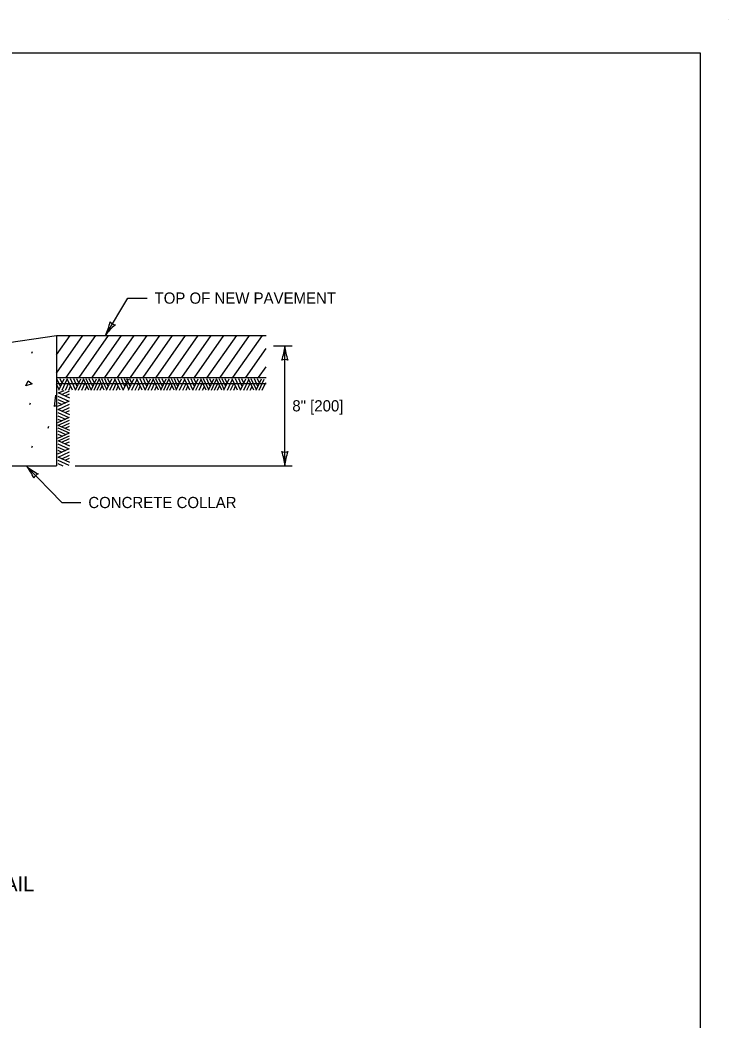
# Model space of a CAD drawing. Extents: x 49991.4 to 50021, y 49987.6 to 50011.4.
# Drawn here: x 50013.11 to 50016.9, y 49993.82 to 49999.18 of the extents above; entities that cross this region are included whole.
import ezdxf

# ---------------------------------------------------------------- set-up
doc = ezdxf.new("R2010")
doc.units = 0
for name, color, linetype in [('Level 1', 7, 'Continuous'), ('Level 2', 7, 'Continuous'), ('Level 3', 7, 'Continuous')]:
    doc.layers.add(name, color=color, linetype=linetype)

msp = doc.modelspace()

# ---------------------------------------------------------------- linework, layer by layer
at = {"layer": 'Level 1'}
for p, q in [((50016.9001, 49999.1756), (50016.9001, 49999.1756)), ((50012.9239, 49997.4313), (50013.3039, 49997.4869)), ((50013.3035, 49997.3834), (50013.3759, 49997.4869)), ((50013.3035, 49997.2853), (50013.4448, 49997.4869)), ((50013.3039, 49997.4869), (50014.4263, 49997.4869)), ((50013.3039, 49997.4869), (50013.3039, 49996.7892)), ((50013.3558, 49997.2621), (50013.5133, 49997.4869)), ((50013.425, 49997.2627), (50013.5817, 49997.4865)), ((50013.4934, 49997.2623), (50013.6507, 49997.4869)), ((50013.5619, 49997.2621), (50013.7193, 49997.4869)), ((50013.6303, 49997.2617), (50013.788, 49997.4869)), ((50013.6767, 49997.4869), (50013.6767, 49997.4869)), ((50013.6992, 49997.2619), (50013.8567, 49997.4869)), ((50013.7678, 49997.2619), (50013.9253, 49997.4869)), ((50013.8365, 49997.2619), (50013.9941, 49997.4869)), ((50013.9052, 49997.2619), (50014.0627, 49997.4869)), ((50013.9738, 49997.2619), (50014.1314, 49997.4869)), ((50014.0425, 49997.2619), (50014.2, 49997.4869)), ((50014.1111, 49997.2619), (50014.2687, 49997.4869)), ((50014.1798, 49997.2619), (50014.3374, 49997.4869)), ((50014.2485, 49997.2619), (50014.406, 49997.4869)), ((50014.3171, 49997.2619), (50014.4263, 49997.4178)), ((50013.1709, 49997.3921), (50013.1752, 49997.4018)), ((50014.3859, 49997.2619), (50014.4263, 49997.3197)), ((50013.3039, 49997.2619), (50013.6773, 49997.2619)), ((50013.325, 49997.2138), (50013.3058, 49997.2549)), ((50013.3157, 49997.1936), (50013.3441, 49997.2549)), ((50013.3332, 49997.2315), (50013.3226, 49997.2549)), ((50013.3885, 49997.1936), (50013.3599, 49997.2549)), ((50013.4052, 49997.1953), (50013.3776, 49997.2549)), ((50013.414, 49997.2143), (50013.3953, 49997.2549)), ((50013.4045, 49997.1936), (50013.4329, 49997.2549)), ((50013.422, 49997.2322), (50013.4117, 49997.2549)), ((50013.4759, 49997.1936), (50013.4472, 49997.2549)), ((50013.4898, 49997.1955), (50013.4622, 49997.2549)), ((50013.498, 49997.2132), (50013.4788, 49997.2549)), ((50013.4889, 49997.1936), (50013.5173, 49997.2551)), ((50013.5066, 49997.2317), (50013.4959, 49997.2549)), ((50013.5594, 49997.1936), (50013.531, 49997.2549)), ((50013.5594, 49997.2263), (50013.5462, 49997.2549)), ((50013.5805, 49997.2138), (50013.5613, 49997.2549)), ((50013.5712, 49997.1936), (50013.5996, 49997.2549)), ((50013.5887, 49997.2315), (50013.578, 49997.2549)), ((50013.6439, 49997.1936), (50013.6154, 49997.2549)), ((50013.6607, 49997.1953), (50013.6331, 49997.2549)), ((50013.6695, 49997.2143), (50013.6508, 49997.2549)), ((50013.6599, 49997.1936), (50013.6883, 49997.2549)), ((50013.6775, 49997.2322), (50013.6672, 49997.2549)), ((50013.6773, 49997.2619), (50014.4263, 49997.2619)), ((50013.6984, 49997.2138), (50013.6792, 49997.2549)), ((50013.6891, 49997.1936), (50013.7175, 49997.2549)), ((50013.7066, 49997.2315), (50013.696, 49997.2549)), ((50013.7619, 49997.1936), (50013.7333, 49997.2549)), ((50013.7786, 49997.1953), (50013.751, 49997.2549)), ((50013.7874, 49997.2143), (50013.7687, 49997.2549)), ((50013.7779, 49997.1936), (50013.8063, 49997.2549)), ((50013.7954, 49997.2322), (50013.7851, 49997.2549)), ((50013.8493, 49997.1936), (50013.8206, 49997.2549)), ((50013.8632, 49997.1955), (50013.8356, 49997.2549)), ((50013.8714, 49997.2132), (50013.8522, 49997.2549)), ((50013.8623, 49997.1936), (50013.8907, 49997.2551)), ((50013.88, 49997.2317), (50013.8693, 49997.2549)), ((50013.9328, 49997.1936), (50013.9044, 49997.2549)), ((50013.9328, 49997.2263), (50013.9196, 49997.2549)), ((50013.9539, 49997.2138), (50013.9347, 49997.2549)), ((50013.9446, 49997.1936), (50013.973, 49997.2549)), ((50013.9621, 49997.2315), (50013.9514, 49997.2549)), ((50014.0173, 49997.1936), (50013.9888, 49997.2549)), ((50014.0341, 49997.1953), (50014.0065, 49997.2549)), ((50014.0429, 49997.2143), (50014.0242, 49997.2549)), ((50014.0333, 49997.1936), (50014.0617, 49997.2549)), ((50014.0509, 49997.2322), (50014.0406, 49997.2549)), ((50014.1048, 49997.1936), (50014.076, 49997.2549)), ((50014.1187, 49997.1955), (50014.0911, 49997.2549)), ((50014.1269, 49997.2132), (50014.1076, 49997.2549)), ((50014.1177, 49997.1936), (50014.1461, 49997.2551)), ((50014.1355, 49997.2317), (50014.1248, 49997.2549)), ((50014.1882, 49997.1936), (50014.1598, 49997.2549)), ((50014.1882, 49997.2263), (50014.1751, 49997.2549)), ((50014.2094, 49997.2138), (50014.1901, 49997.2549)), ((50014.2, 49997.1936), (50014.2284, 49997.2549)), ((50014.2176, 49997.2315), (50014.2069, 49997.2549)), ((50014.2728, 49997.1936), (50014.2442, 49997.2549)), ((50014.2896, 49997.1953), (50014.2619, 49997.2549)), ((50014.2983, 49997.2143), (50014.2797, 49997.2549)), ((50014.2888, 49997.1936), (50014.3172, 49997.2549)), ((50014.3063, 49997.2322), (50014.296, 49997.2549)), ((50014.3602, 49997.1936), (50014.3315, 49997.2549)), ((50014.3741, 49997.1955), (50014.3465, 49997.2549)), ((50014.3823, 49997.2132), (50014.3631, 49997.2549)), ((50014.3732, 49997.1936), (50014.4016, 49997.2551)), ((50014.3909, 49997.2317), (50014.3802, 49997.2549)), ((50013.3039, 49997.2304), (50013.6773, 49997.2304)), ((50013.3174, 49997.1974), (50013.3039, 49997.2263)), ((50013.334, 49997.1936), (50013.3612, 49997.2521)), ((50013.3515, 49997.1936), (50013.37, 49997.2334)), ((50013.3689, 49997.1936), (50013.3786, 49997.2147)), ((50013.4214, 49997.1936), (50013.4485, 49997.2519)), ((50013.439, 49997.1936), (50013.4573, 49997.2334)), ((50013.4569, 49997.1936), (50013.4662, 49997.2141)), ((50013.5041, 49997.1936), (50013.5315, 49997.253)), ((50013.5209, 49997.1936), (50013.5399, 49997.2353)), ((50013.5371, 49997.1936), (50013.5481, 49997.2178)), ((50013.5729, 49997.1974), (50013.5594, 49997.2263)), ((50013.5895, 49997.1936), (50013.6167, 49997.2521)), ((50013.607, 49997.1936), (50013.6255, 49997.2334)), ((50013.6243, 49997.1936), (50013.634, 49997.2147)), ((50013.6773, 49997.2304), (50014.4263, 49997.2304)), ((50013.6908, 49997.1974), (50013.6773, 49997.2263)), ((50013.7074, 49997.1936), (50013.7346, 49997.2521)), ((50013.7249, 49997.1936), (50013.7434, 49997.2334)), ((50013.7423, 49997.1936), (50013.752, 49997.2147)), ((50013.7948, 49997.1936), (50013.8219, 49997.2519)), ((50013.8124, 49997.1936), (50013.8307, 49997.2334)), ((50013.8303, 49997.1936), (50013.8396, 49997.2141)), ((50013.8775, 49997.1936), (50013.9049, 49997.253)), ((50013.8943, 49997.1936), (50013.9133, 49997.2353)), ((50013.9105, 49997.1936), (50013.9215, 49997.2178)), ((50013.9463, 49997.1974), (50013.9328, 49997.2263)), ((50013.9629, 49997.1936), (50013.9901, 49997.2521)), ((50013.9804, 49997.1936), (50013.9989, 49997.2334)), ((50013.9977, 49997.1936), (50014.0074, 49997.2147)), ((50014.0503, 49997.1936), (50014.0774, 49997.2519)), ((50014.0678, 49997.1936), (50014.0861, 49997.2334)), ((50014.0857, 49997.1936), (50014.0951, 49997.2141)), ((50014.133, 49997.1936), (50014.1604, 49997.253)), ((50014.1497, 49997.1936), (50014.1688, 49997.2353)), ((50014.1659, 49997.1936), (50014.177, 49997.2178)), ((50014.2017, 49997.1974), (50014.1882, 49997.2263)), ((50014.2183, 49997.1936), (50014.2456, 49997.2521)), ((50014.2358, 49997.1936), (50014.2543, 49997.2334)), ((50014.2532, 49997.1936), (50014.2629, 49997.2147)), ((50014.3058, 49997.1936), (50014.3328, 49997.2519)), ((50014.3233, 49997.1936), (50014.3416, 49997.2334)), ((50014.3412, 49997.1936), (50014.3505, 49997.2141)), ((50014.3884, 49997.1936), (50014.4159, 49997.253)), ((50014.4052, 49997.1936), (50014.4242, 49997.2353)), ((50013.311, 49997.1807), (50013.3723, 49997.1523)), ((50013.311, 49997.1624), (50013.3695, 49997.1351)), ((50013.3148, 49997.179), (50013.3437, 49997.1925)), ((50013.3312, 49997.1713), (50013.3723, 49997.1906)), ((50013.3489, 49997.1631), (50013.3723, 49997.1738)), ((50013.1601, 49997.1171), (50013.1644, 49997.1268)), ((50013.311, 49997.1449), (50013.3508, 49997.1264)), ((50013.311, 49997.1079), (50013.3723, 49997.1365)), ((50013.311, 49997.1275), (50013.3321, 49997.1178)), ((50013.3127, 49997.0911), (50013.3723, 49997.1188)), ((50013.3317, 49997.0824), (50013.3723, 49997.101)), ((50013.311, 49997.0919), (50013.3723, 49997.0635)), ((50013.311, 49997.0749), (50013.3693, 49997.0479)), ((50013.311, 49997.0574), (50013.3508, 49997.0391)), ((50013.311, 49997.0205), (50013.3723, 49997.0492)), ((50013.3496, 49997.0744), (50013.3723, 49997.0847)), ((50013.2586, 49996.9915), (50013.2629, 49997.0013)), ((50013.311, 49997.0395), (50013.3315, 49997.0302)), ((50013.311, 49997.0075), (50013.3725, 49996.9791)), ((50013.311, 49996.9923), (50013.3704, 49996.9648)), ((50013.3129, 49997.0065), (50013.3723, 49997.0342)), ((50013.3306, 49996.9984), (50013.3723, 49997.0176)), ((50013.3491, 49996.9898), (50013.3723, 49997.0005)), ((50013.311, 49996.9755), (50013.3527, 49996.9564)), ((50013.311, 49996.937), (50013.3723, 49996.9654)), ((50013.311, 49996.9593), (50013.3352, 49996.9483)), ((50013.3148, 49996.9235), (50013.3437, 49996.937)), ((50013.3312, 49996.9159), (50013.3723, 49996.9351)), ((50013.3437, 49996.937), (50013.3723, 49996.9502)), ((50013.1709, 49996.8864), (50013.1752, 49996.8961)), ((50013.311, 49996.9252), (50013.3723, 49996.8968)), ((50013.311, 49996.9069), (50013.3695, 49996.8797)), ((50013.311, 49996.8894), (50013.3508, 49996.8709)), ((50013.311, 49996.8524), (50013.3723, 49996.881)), ((50013.3489, 49996.9077), (50013.3723, 49996.9183)), ((50013.311, 49996.8721), (50013.3321, 49996.8623)), ((50013.311, 49996.8364), (50013.3723, 49996.808)), ((50013.3127, 49996.8357), (50013.3723, 49996.8633)), ((50013.3317, 49996.8269), (50013.3723, 49996.8456)), ((50013.3496, 49996.8189), (50013.3723, 49996.8292)), ((50012.8258, 49996.7892), (50013.3039, 49996.7892)), ((50013.311, 49996.8195), (50013.3693, 49996.7924)), ((50013.311, 49996.802), (50013.3374, 49996.7899))]:
    msp.add_line(p, q, dxfattribs=at)
msp.add_lwpolyline([(49999.3835, 49998.9992), (50016.7501, 49998.9992), (50016.7501, 49987.7988), (49999.3835, 49987.7988)], close=True, dxfattribs=at)
for points in [[(50013.1386, 49997.2173), (50013.1516, 49997.2443), (50013.1733, 49997.2281), (50013.1386, 49997.2173)], [(50013.2918, 49997.1059), (50013.3004, 49997.1678), (50013.3039, 49997.1641)], [(50013.3039, 49997.1114), (50013.2928, 49997.1063)]]:
    msp.add_lwpolyline(points, dxfattribs=at)
at = {"layer": 'Level 3'}
for p, q in [((50013.565, 49997.4869), (50013.6858, 49997.6869)), ((50013.6858, 49997.6869), (50013.7885, 49997.6869)), ((50014.4663, 49997.4313), (50014.5663, 49997.4313)), ((50014.5263, 49996.7892), (50014.5263, 49997.4313)), ((50013.1407, 49996.7892), (50013.3311, 49996.5927)), ((50013.4039, 49996.7892), (50014.5663, 49996.7892)), ((50013.3311, 49996.5927), (50013.4338, 49996.5927))]:
    msp.add_line(p, q, dxfattribs=at)
for centre, radius, start, end in [((50013.3599, 49997.5974), 0.233, 331.6942, 350.9441), ((50013.7504, 49997.3642), 0.2223, 126.3229, 146.5064), ((50013.6313, 49997.5967), 0.0548, 221.0057, 256.7281), ((50014.3042, 49997.4405), 0.2223, 337.456, 357.6395), ((50014.759, 49997.4428), 0.233, 182.8273, 202.0772), ((50014.5263, 49997.3031), 0.0548, 72.1388, 107.8612), ((50014.5263, 49996.9174), 0.0548, 252.1388, 287.8612), ((50014.2936, 49996.7777), 0.233, 2.8273, 22.0772), ((50014.7484, 49996.78), 0.2223, 157.456, 177.6395), ((50012.9749, 49996.6411), 0.2223, 21.5692, 41.7527), ((50013.2998, 49996.9594), 0.233, 226.9405, 246.1904), ((50013.23, 49996.6971), 0.0548, 116.2521, 151.9744)]:
    msp.add_arc(centre, radius, start, end, dxfattribs=at)

# ---------------------------------------------------------------- texts
at = {"layer": 'Level 2'}
for s, height, p in [('TOP OF NEW PAVEMENT', 0.06, (50013.8285, 49997.6569)), ('8" [200]', 0.06, (50014.5663, 49997.0803)), ('CONCRETE COLLAR', 0.06, (50013.4738, 49996.5627)), ('VALVE BOX ADJUSTMENT DETAIL', 0.08, (50011.4303, 49994.5111))]:
    msp.add_text(s, height=height, dxfattribs=at).set_placement(p)

doc.saveas('drawing.dxf')
